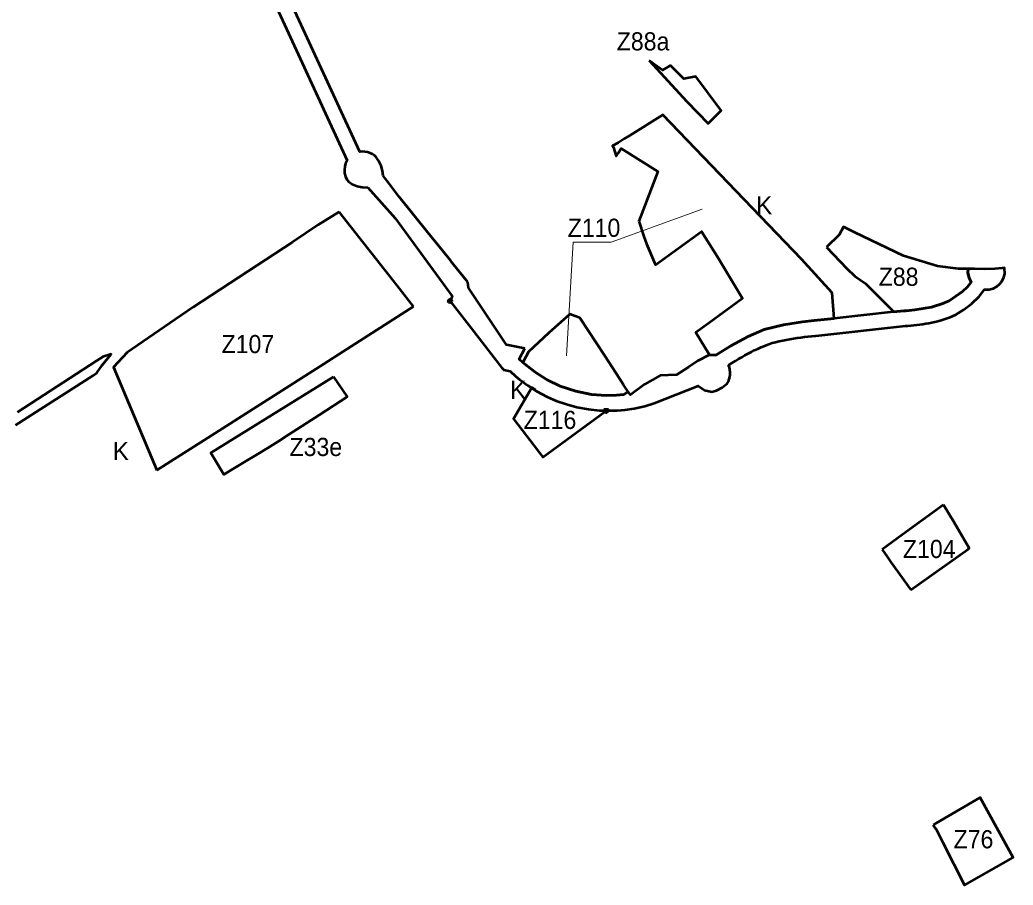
# Model space of a CAD drawing. Extents: x -650246 to -642674, y -1074280 to -1066767.
# Drawn here: x -648043 to -646732, y -1072931 to -1071788 of the extents above; entities that cross this region are included whole.
import ezdxf

# ---------------------------------------------------------------- set-up
doc = ezdxf.new("R2010")
doc.units = 0
doc.header["$LTSCALE"] = 9.6
doc.header["$PDMODE"] = 32
doc.header["$PDSIZE"] = 4.8
for name, color, linetype, lineweight in [('44', 7, 'Continuous', 53), ('45', 7, 'Continuous', 53), ('46', 7, 'Continuous', 13), ('48', 7, 'Continuous', 13)]:
    doc.layers.add(name, color=color, linetype=linetype, lineweight=lineweight)

msp = doc.modelspace()

# ---------------------------------------------------------------- linework, layer by layer
at = {"layer": '44'}
msp.add_line((-646978.602, -1072088.66), (-646951.95, -1072116.84), dxfattribs=at)
for points in [[(-647782.97, -1071619.278), (-647769.498, -1071636.647), (-647758.994, -1071653.513), (-647743.48, -1071687.426), (-647611.514, -1071974.086)], [(-647563.77, -1071994.38), (-647564.751, -1071987.939), (-647566.62, -1071981.3), (-647569.422, -1071974.943), (-647573.283, -1071969.627), (-647575.415, -1071967.709), (-647577.881, -1071965.979), (-647581.036, -1071964.346), (-647584.363, -1071963.196), (-647588.064, -1071962.51), (-647591.518, -1071962.387), (-647594.731, -1071962.714), (-647725.614, -1071678.405), (-647726.774, -1071675.885), (-647725.629, -1071678.373)], [(-647184.81, -1071848.61), (-647185.62, -1071849.12), (-647194.96, -1071854.93), (-647205.62, -1071847.24), (-647212.66, -1071842.15)], [(-647212.66, -1071842.15), (-647163.08, -1071896.13), (-647135.015, -1071925.145), (-647135.015, -1071925.145)], [(-647135.015, -1071925.145), (-647135.015, -1071925.145), (-647117.709, -1071908.3), (-647151.07, -1071863.08), (-647167.15, -1071866.22), (-647184.81, -1071848.61)], [(-647611.514, -1071974.086), (-647613.455, -1071978.031), (-647614.654, -1071982.238), (-647615.083, -1071986.65), (-647614.76, -1071990.762), (-647613.637, -1071995.081), (-647611.779, -1071999.069), (-647609.808, -1072001.962)], [(-647542.57, -1072021.99), (-647558.97, -1072000.62), (-647563.77, -1071994.38)], [(-647609.808, -1072001.962), (-647604.924, -1072005.628), (-647598.384, -1072007.852), (-647591.564, -1072009.255), (-647584.202, -1072009.747)], [(-647584.202, -1072009.747), (-647547.916, -1072050.439), (-647473.022, -1072153.375), (-647475.57, -1072159.74)], [(-647452.23, -1072134.91), (-647472.86, -1072109.13), (-647474.72, -1072106.81), (-647485.6, -1072093.2), (-647504.73, -1072069.29), (-647542.57, -1072021.99)], [(-646790.432, -1072129.195), (-646791.977, -1072122.305), (-646791.84, -1072117.172), (-646804.27, -1072116.98), (-646832.01, -1072113.66), (-646876.83, -1072100.12), (-646941.054, -1072069.172), (-646956.04, -1072061.95), (-646962.041, -1072072.379), (-646978.602, -1072088.66)], [(-646951.95, -1072116.84), (-646941.45, -1072126.84), (-646927.14, -1072136.74), (-646891.05, -1072172.79), (-646890.044, -1072174.056), (-646876.712, -1072172.592), (-646873.495, -1072172.799), (-646862.09, -1072171.444), (-646840.102, -1072167.623), (-646825.169, -1072163.164), (-646816.74, -1072159.571), (-646799, -1072147), (-646792.58, -1072140.847), (-646787.481, -1072134.643), (-646790.432, -1072129.195)], [(-646808.466, -1072177.78), (-646797.713, -1072171.151), (-646787.223, -1072163.402), (-646777.129, -1072153.576), (-646770.057, -1072144.677), (-646763.959, -1072144.535), (-646758.736, -1072143.137), (-646753.929, -1072140.612), (-646750.164, -1072137.467), (-646747.39, -1072134.069), (-646744.554, -1072128.415), (-646743.411, -1072123.612), (-646743.596, -1072115.985), (-646746.547, -1072116.221), (-646756.298, -1072117), (-646769.668, -1072117.517), (-646783.449, -1072117.302), (-646791.84, -1072117.172)], [(-646791.84, -1072117.172), (-646791.977, -1072122.305), (-646790.432, -1072129.195)], [(-647376.68, -1072222.29), (-647401.221, -1072217.342), (-647451.21, -1072142.08), (-647452.23, -1072134.91)], [(-646790.432, -1072129.195), (-646787.481, -1072134.643), (-646792.58, -1072140.847), (-646799, -1072147), (-646816.74, -1072159.571), (-646825.169, -1072163.164), (-646840.102, -1072167.623), (-646862.09, -1072171.444), (-646873.495, -1072172.799), (-646876.712, -1072172.592), (-646890.044, -1072174.056), (-646968.503, -1072182.672)], [(-647475.57, -1072159.74), (-647447.73, -1072195.72), (-647407.34, -1072247.93)], [(-646835.538, -1072187.097), (-646831.517, -1072186.103), (-646827.501, -1072184.997), (-646823.496, -1072183.769), (-646819.509, -1072182.408), (-646815.549, -1072180.906), (-646811.621, -1072179.254), (-646808.466, -1072177.78)], [(-646968.503, -1072182.672), (-646995.137, -1072185.597), (-647010.148, -1072187.308), (-647035.515, -1072191.104), (-647060.973, -1072197.439), (-647082.249, -1072206.591), (-647104.989, -1072219.005), (-647124.81, -1072231.168), (-647133, -1072230.754), (-647148.71, -1072238.76)], [(-647017.46, -1072208.427), (-647012.612, -1072207.773), (-647007.734, -1072207.162), (-647002.826, -1072206.583), (-646997.894, -1072206.024), (-646992.937, -1072205.475), (-646874.517, -1072192.471), (-646871.271, -1072192.675)], [(-646871.271, -1072192.675), (-646867.371, -1072192.234), (-646867.32, -1072192.228), (-646863.448, -1072191.771), (-646859.506, -1072191.276), (-646855.545, -1072190.741), (-646851.567, -1072190.155)], [(-646851.567, -1072190.155), (-646847.575, -1072189.507), (-646843.569, -1072188.789), (-646843.535, -1072188.782), (-646839.556, -1072187.988), (-646835.538, -1072187.097)], [(-647108.131, -1072244.373), (-647103.164, -1072241.306), (-647098.944, -1072238.718), (-647094.737, -1072236.177), (-647090.531, -1072233.695), (-647086.322, -1072231.285), (-647082.102, -1072228.962), (-647077.867, -1072226.739), (-647073.611, -1072224.631), (-647069.33, -1072222.651), (-647064.868, -1072220.746), (-647054.841, -1072216.479), (-647050.344, -1072215.107), (-647045.786, -1072213.858), (-647041.174, -1072212.723), (-647036.512, -1072211.693), (-647031.807, -1072210.758), (-647027.061, -1072209.91), (-647022.278, -1072209.136), (-647017.46, -1072208.427)], [(-648049.33, -1072323.77), (-647946.88, -1072257.82), (-647941.77, -1072254.45), (-647934.9, -1072244.55), (-647923.16, -1072229.85), (-647933.95, -1072233.18), (-647942.21, -1072238.54), (-648046.69, -1072306.3)], [(-647240.55, -1072279.42), (-647246.206, -1072283.328), (-647255.671, -1072284.192), (-647269.579, -1072284.489), (-647288.769, -1072283.003), (-647309.416, -1072278.875), (-647330.032, -1072271.935), (-647347.382, -1072263.623), (-647363.317, -1072253.632), (-647363.786, -1072253.254), (-647379.422, -1072240.675), (-647384.567, -1072236.256), (-647376.68, -1072222.29)], [(-647148.71, -1072238.76), (-647160.91, -1072246.82), (-647176.7, -1072257.24), (-647198.3, -1072258.09), (-647218.35, -1072269.67), (-647237.6, -1072283.78), (-647240.55, -1072279.42)], [(-647407.34, -1072247.93), (-647404.45, -1072250.66), (-647396.25, -1072252.14), (-647389.072, -1072258.845)], [(-647389.072, -1072258.845), (-647383.813, -1072263.219), (-647372.858, -1072271.363), (-647361.521, -1072278.584), (-647347.369, -1072286.111)], [(-647205.975, -1072294.599), (-647148.171, -1072271.47), (-647139.697, -1072277.484), (-647130.12, -1072279.44), (-647123.774, -1072277.899)], [(-647123.774, -1072277.899), (-647116.323, -1072273.885), (-647109.812, -1072268.588)], [(-647347.369, -1072286.111), (-647335.382, -1072291.341), (-647321.953, -1072296.073), (-647308.157, -1072299.786), (-647292.715, -1072302.646), (-647278.108, -1072304.147), (-647271.395, -1072304.452), (-647269.52, -1072307.17), (-647265.793, -1072304.439)], [(-647265.793, -1072304.439), (-647255.16, -1072304.123), (-647244.428, -1072303.192), (-647232.368, -1072301.4), (-647218.5, -1072298.335), (-647205.975, -1072294.599)]]:
    msp.add_lwpolyline(points, dxfattribs=at)
msp.add_arc((-647130.12, -1072255.012), 24.428, 326.23773, 25.81772, dxfattribs=at)
msp.add_point((-647475.57, -1072159.74), dxfattribs=at)
at = {"layer": '45'}
for points in [[(-647226.41, -1072054.11), (-647219.64, -1072074.29), (-647216.23, -1072084.14), (-647204.78, -1072110.92), (-647204.38, -1072111.87), (-647143.76, -1072067.69), (-647122.33, -1072101.34), (-647089.54, -1072156.53), (-647134.17, -1072188.95), (-647151.05, -1072201.21), (-647138.65, -1072221.5), (-647133, -1072230.754), (-647124.81, -1072231.168), (-647104.989, -1072219.005), (-647082.249, -1072206.591), (-647060.973, -1072197.439), (-647035.515, -1072191.104), (-647010.148, -1072187.308), (-646995.137, -1072185.597), (-646968.503, -1072182.672), (-646971.283, -1072148.82), (-647011.762, -1072104.502), (-647194.903, -1071913.941), (-647238.1, -1071941), (-647245.71, -1071945.77), (-647253.67, -1071950.76), (-647261.12, -1071954.82), (-647259.7, -1071957.06), (-647256.53, -1071968.64), (-647253.85, -1071964.38), (-647249.92, -1071958.12), (-647201.53, -1071988.71)], [(-647226.41, -1072054.11), (-647219.64, -1072074.29), (-647216.23, -1072084.14), (-647204.78, -1072110.92), (-647204.38, -1072111.87), (-647143.76, -1072067.69), (-647122.33, -1072101.34), (-647089.54, -1072156.53), (-647134.17, -1072188.95), (-647151.05, -1072201.21), (-647138.65, -1072221.5), (-647133, -1072230.754), (-647124.81, -1072231.168), (-647104.989, -1072219.005), (-647082.249, -1072206.591), (-647060.973, -1072197.439), (-647035.515, -1072191.104), (-647010.148, -1072187.308), (-646995.137, -1072185.597), (-646968.503, -1072182.672), (-646971.283, -1072148.82), (-647011.762, -1072104.502), (-647194.903, -1071913.941), (-647238.1, -1071941), (-647245.71, -1071945.77), (-647253.67, -1071950.76), (-647261.12, -1071954.82), (-647259.7, -1071957.06), (-647256.53, -1071968.64), (-647253.85, -1071964.38), (-647249.92, -1071958.12), (-647201.53, -1071988.71)], [(-647246.563, -1072270.214), (-647251.85, -1072262.12), (-647271.38, -1072232.23), (-647304.32, -1072181.81), (-647310.33, -1072179.58), (-647317.33, -1072176.99), (-647345.42, -1072201.58), (-647372.1, -1072226.89), (-647375.551, -1072233.387), (-647379.422, -1072240.675), (-647363.317, -1072253.632), (-647347.382, -1072263.623), (-647330.032, -1072271.935), (-647309.416, -1072278.875), (-647288.769, -1072283.003), (-647269.579, -1072284.489), (-647255.671, -1072284.192), (-647246.206, -1072283.328), (-647240.55, -1072279.42)], [(-647246.563, -1072270.214), (-647251.85, -1072262.12), (-647271.38, -1072232.23), (-647304.32, -1072181.81), (-647310.33, -1072179.58), (-647317.33, -1072176.99), (-647345.42, -1072201.58), (-647372.1, -1072226.89), (-647375.551, -1072233.387), (-647379.422, -1072240.675), (-647363.317, -1072253.632), (-647347.382, -1072263.623), (-647330.032, -1072271.935), (-647309.416, -1072278.875), (-647288.769, -1072283.003), (-647269.579, -1072284.489), (-647255.671, -1072284.192), (-647246.206, -1072283.328), (-647240.55, -1072279.42)], [(-647629.67, -1072259.82), (-647611.51, -1072286.26), (-647648.09, -1072309.95), (-647688.26, -1072336.06), (-647702.35, -1072345.14), (-647716.62, -1072353.95), (-647730.97, -1072362.6), (-647745.32, -1072371.26), (-647759.68, -1072379.91), (-647774.04, -1072388.57), (-647791.198, -1072360.119)], [(-646837.81, -1072851.3), (-646836.5, -1072853.76), (-646833.67, -1072857.15), (-646824.89, -1072874.66), (-646796.68, -1072930.92), (-646732.28, -1072894.29), (-646775.85, -1072815.39), (-646834.08, -1072849.15)], [(-646837.81, -1072851.3), (-646836.5, -1072853.76), (-646833.67, -1072857.15), (-646824.89, -1072874.66), (-646796.68, -1072930.92), (-646732.28, -1072894.29), (-646775.85, -1072815.39), (-646834.08, -1072849.15)]]:
    msp.add_lwpolyline(points, close=True, dxfattribs=at)
for points in [[(-647621.97, -1072041.73), (-647649.76, -1072059.06), (-647683.63, -1072081.94), (-647730.53, -1072112.84), (-647814.58, -1072167.67), (-647845.58, -1072188.94), (-647901.91, -1072227.6), (-647919.68, -1072247.09), (-647862.615, -1072383.084)], [(-647523.71, -1072167.071), (-647545.44, -1072139.35), (-647621.97, -1072041.73)], [(-647862.615, -1072383.084), (-647800.2, -1072343.615), (-647642.504, -1072242.974), (-647616.719, -1072226.154), (-647523.71, -1072167.071)], [(-647362.702, -1072277.035), (-647367.686, -1072273.861), (-647391.761, -1072315.201), (-647353.041, -1072365.971), (-647270.701, -1072305.621), (-647266.974, -1072302.89), (-647272.576, -1072302.903)], [(-646824.42, -1072428.58), (-646878.91, -1072468.54), (-646905.18, -1072487.8)], [(-646824.42, -1072428.58), (-646878.91, -1072468.54), (-646905.18, -1072487.8)], [(-646867.283, -1072540.984), (-646791.569, -1072487.198), (-646790.354, -1072486.136), (-646810.77, -1072451.09), (-646824.42, -1072428.58)], [(-646867.283, -1072540.984), (-646791.569, -1072487.198), (-646790.354, -1072486.136), (-646810.77, -1072451.09), (-646824.42, -1072428.58)], [(-646905.18, -1072487.8), (-646898.1, -1072498.02), (-646893.64, -1072504.45), (-646867.283, -1072540.984)], [(-646905.18, -1072487.8), (-646898.1, -1072498.02), (-646893.64, -1072504.45), (-646867.283, -1072540.984)]]:
    msp.add_lwpolyline(points, dxfattribs=at)
msp.add_arc((-646767.624, -1072120.384), 24.428, 264.28146, 264.89913, dxfattribs=at)
msp.add_arc((-646767.624, -1072120.384), 24.428, 264.28146, 264.89913, dxfattribs=at)
at = {"layer": '46'}
msp.add_lwpolyline([(-647321.863, -1072232.262), (-647313.149, -1072082.081), (-647262.801, -1072082.081), (-647142.741, -1072038.48)], dxfattribs=at)
msp.add_lwpolyline([(-647321.863, -1072232.262), (-647313.149, -1072082.081), (-647262.801, -1072082.081), (-647142.741, -1072038.48)], dxfattribs=at)

# ---------------------------------------------------------------- texts
at = {"layer": '44', "width": 0.95}
for s, p in [('Z88a', (-647255.564, -1071828.861)), ('Z88', (-646909.741, -1072139.634)), ('Z88', (-646909.741, -1072139.634))]:
    msp.add_text(s, height=24, dxfattribs=at).set_placement(p)
at = {"layer": '46', "width": 0.95}
for s, p in [('Z110', (-647320.328, -1072074.974)), ('Z110', (-647320.328, -1072074.974)), ('Z107', (-647777.22, -1072228.544)), ('Z116', (-647378.432, -1072328.636)), ('Z33e', (-647687.519, -1072364.366)), ('Z104', (-646877.745, -1072499.058)), ('Z104', (-646877.745, -1072499.058)), ('Z76', (-646810.899, -1072882.315)), ('Z76', (-646810.899, -1072882.315))]:
    msp.add_text(s, height=24, dxfattribs=at).set_placement(p)
at = {"layer": '48'}
for p in [(-647071.498, -1072045.307), (-647396.507, -1072288.9), (-647920.872, -1072369.761)]:
    msp.add_text('K', height=24, dxfattribs=at).set_placement(p)

doc.saveas('drawing.dxf')
